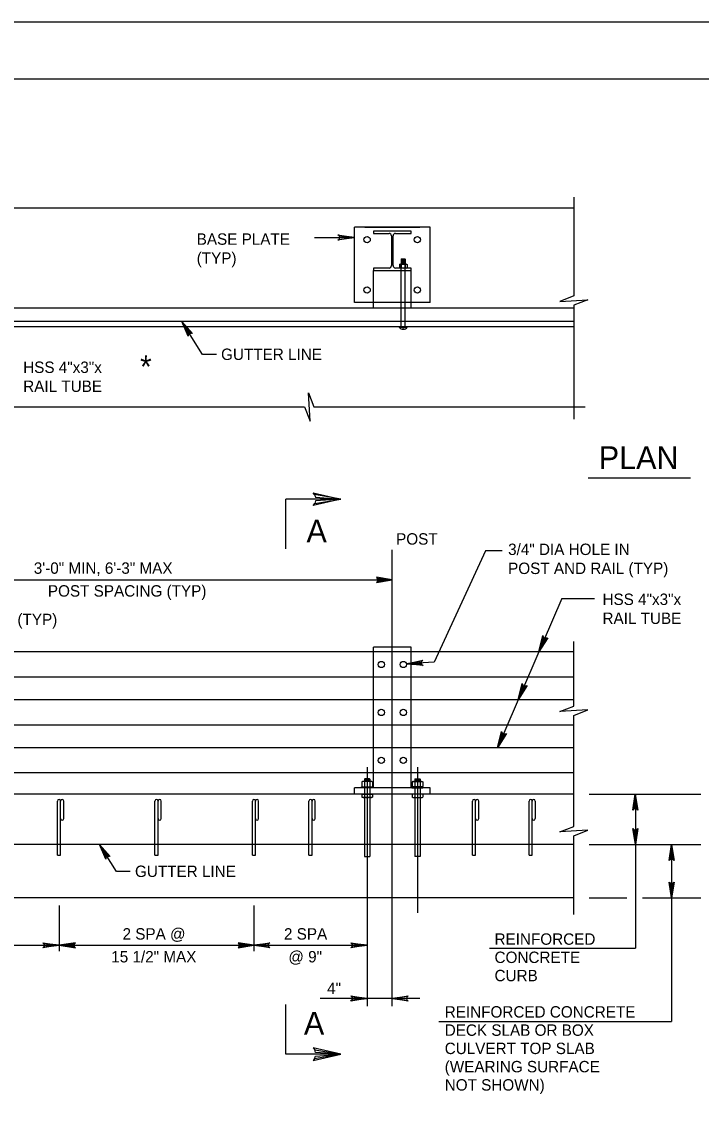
# Model space of a CAD drawing. Extents: x 641054 to 641910, y 298137 to 299325.
# Drawn here: x 641229.9 to 641408.6, y 299039.1 to 299325.4 of the extents above; entities that cross this region are included whole.
import ezdxf

# ---------------------------------------------------------------- set-up
doc = ezdxf.new("R2010")
doc.units = 0
for name, color, linetype in [('1', 7, 'Continuous'), ('2', 7, 'Continuous'), ('Default', 7, 'Continuous'), ('PLT-BNDY', 7, 'Continuous')]:
    doc.layers.add(name, color=color, linetype=linetype)

msp = doc.modelspace()

# ---------------------------------------------------------------- linework, layer by layer
at = {"layer": '1'}
for p, q in [((641329.41, 299261.63), (641329.28, 299261.55)), ((641329.28, 299261.55), (641329.28, 299260.69)), ((641329.41, 299260.61), (641329.28, 299260.69)), ((641329.41, 299261.63), (641331.13, 299261.63)), ((641329.75, 299262.92), (641329.84, 299263.01)), ((641329.75, 299262.92), (641329.75, 299261.63)), ((641329.75, 299262.92), (641330.79, 299262.92)), ((641329.75, 299262.66), (641330.79, 299262.66)), ((641329.75, 299262.4), (641330.79, 299262.4)), ((641329.75, 299262.14), (641330.79, 299262.14)), ((641329.75, 299261.89), (641330.79, 299261.89)), ((641329.75, 299261.55), (641329.75, 299260.69)), ((641329.84, 299263.01), (641330.7, 299263.01)), ((641329.84, 299262.79), (641330.7, 299262.79)), ((641329.84, 299262.53), (641330.7, 299262.53)), ((641329.84, 299262.27), (641330.7, 299262.27)), ((641329.84, 299262.02), (641330.7, 299262.02)), ((641329.84, 299261.76), (641330.7, 299261.76)), ((641330.79, 299262.92), (641330.7, 299263.01)), ((641330.79, 299262.92), (641330.79, 299261.63)), ((641330.79, 299261.55), (641330.79, 299260.69)), ((641331.13, 299261.63), (641331.26, 299261.55)), ((641331.13, 299260.61), (641331.26, 299260.69)), ((641331.26, 299261.55), (641331.26, 299260.69)), ((641331.13, 299260.61), (641329.41, 299260.61)), ((641330.84, 299245.06), (641329.7, 299245.06)), ((641320.04, 299126.17), (641320.16, 299126.29)), ((641320.04, 299126.17), (641320.04, 299125.57)), ((641321.49, 299126.17), (641320.04, 299126.17)), ((641321.37, 299126.29), (641320.16, 299126.29)), ((641321.49, 299126.17), (641321.37, 299126.29)), ((641321.49, 299126.17), (641321.49, 299125.57)), ((641333.27, 299126.17), (641333.39, 299126.29)), ((641333.27, 299126.17), (641333.27, 299125.57)), ((641333.27, 299126.17), (641334.71, 299126.17)), ((641333.39, 299126.29), (641334.59, 299126.29)), ((641334.71, 299126.17), (641334.59, 299126.29)), ((641334.71, 299126.17), (641334.71, 299125.57)), ((641319.56, 299125.57), (641319.37, 299125.46)), ((641319.37, 299125.46), (641319.37, 299124.25)), ((641319.56, 299124.14), (641319.37, 299124.25)), ((641321.97, 299125.57), (641319.56, 299125.57)), ((641321.49, 299125.81), (641320.04, 299125.81)), ((641320.04, 299125.77), (641320.04, 299105.88)), ((641320.04, 299125.46), (641320.04, 299124.25)), ((641321.37, 299125.99), (641320.16, 299125.99)), ((641321.37, 299125.63), (641320.16, 299125.63)), ((641321.49, 299125.77), (641321.49, 299105.88)), ((641321.49, 299125.46), (641321.49, 299124.25)), ((641321.97, 299125.57), (641322.16, 299125.46)), ((641321.97, 299124.14), (641322.16, 299124.25)), ((641322.16, 299125.46), (641322.16, 299124.25)), ((641332.79, 299125.57), (641332.6, 299125.46)), ((641332.6, 299125.46), (641332.6, 299124.25)), ((641332.79, 299124.14), (641332.6, 299124.25)), ((641332.79, 299125.57), (641335.2, 299125.57)), ((641333.27, 299125.81), (641334.71, 299125.81)), ((641333.27, 299125.77), (641333.27, 299105.88)), ((641333.27, 299125.46), (641333.27, 299124.25)), ((641333.38, 299125.99), (641334.6, 299125.99)), ((641333.38, 299125.63), (641334.6, 299125.63)), ((641334.71, 299125.77), (641334.71, 299105.88)), ((641334.71, 299125.46), (641334.71, 299124.25)), ((641335.2, 299125.57), (641335.38, 299125.46)), ((641335.2, 299124.14), (641335.38, 299124.25)), ((641335.38, 299125.46), (641335.38, 299124.25)), ((641319.37, 299122.24), (641319.37, 299121.45)), ((641319.37, 299122.24), (641322.16, 299122.24)), ((641319.56, 299121.34), (641319.37, 299121.45)), ((641321.97, 299121.34), (641319.56, 299121.34)), ((641320.04, 299122.24), (641320.04, 299121.45)), ((641321.49, 299122.24), (641321.49, 299121.45)), ((641321.97, 299121.34), (641322.16, 299121.45)), ((641322.16, 299122.24), (641322.16, 299121.45)), ((641332.6, 299122.24), (641332.6, 299121.45)), ((641335.38, 299122.24), (641332.6, 299122.24)), ((641332.79, 299121.34), (641332.6, 299121.45)), ((641332.79, 299121.34), (641335.2, 299121.34)), ((641333.27, 299122.24), (641333.27, 299121.45)), ((641334.71, 299122.24), (641334.71, 299121.45)), ((641335.2, 299121.34), (641335.38, 299121.45)), ((641335.38, 299122.24), (641335.38, 299121.45)), ((641320.04, 299105.88), (641321.49, 299105.88)), ((641334.71, 299105.88), (641333.27, 299105.88))]:
    msp.add_line(p, q, dxfattribs=at)
for points in [[(641319.32, 299123.9), (641319.32, 299124.14), (641322.21, 299124.14), (641322.21, 299123.9)], [(641335.44, 299123.9), (641335.44, 299124.14), (641332.54, 299124.14), (641332.54, 299123.9)]]:
    msp.add_lwpolyline(points, close=True, dxfattribs=at)
for points in [[(641235.65, 299083.01), (641235.81, 299082.72), (641239.74, 299082.5), (641235.65, 299083.01), (641235.45, 299083.19), (641239.74, 299082.5), (641235.81, 299082.31), (641235.67, 299082.01), (641239.74, 299082.5), (641235.45, 299081.82), (641235.67, 299082.01)], [(641243.83, 299083.01), (641243.68, 299082.72), (641239.74, 299082.5), (641243.83, 299083.01), (641244.04, 299083.19), (641239.74, 299082.5), (641243.67, 299082.31), (641243.82, 299082.01), (641239.74, 299082.5), (641244.04, 299081.82), (641243.82, 299082.01)], [(641316.67, 299083.01), (641316.83, 299082.72), (641320.76, 299082.5), (641316.67, 299083.01), (641316.46, 299083.19), (641320.76, 299082.5), (641316.83, 299082.31), (641316.69, 299082.01), (641320.76, 299082.5), (641316.46, 299081.82), (641316.69, 299082.01)], [(641316.67, 299069.03), (641316.83, 299068.73), (641320.76, 299068.52), (641316.67, 299069.03), (641316.46, 299069.21), (641320.76, 299068.52), (641316.83, 299068.32), (641316.69, 299068.03), (641320.76, 299068.52), (641316.46, 299067.83), (641316.69, 299068.03)]]:
    msp.add_lwpolyline(points, dxfattribs=at)
for centre, radius, start, end in [((641329.52, 299261.22), 0.409, 54.2974, 89.9999), ((641329.52, 299261.02), 0.409, 269.9985, 305.701), ((641330.27, 299259.85), 1.77, 73.0653, 106.9335), ((641330.27, 299262.39), 1.77, 253.0634, 286.9317), ((641331.03, 299261.22), 0.409, 89.9993, 125.7017), ((641331.03, 299261.02), 0.409, 234.2959, 269.9983), ((641319.71, 299124.99), 0.573, 54.2983, 90.0007), ((641319.71, 299124.72), 0.573, 270.0017, 305.7041), ((641320.76, 299123.08), 2.48, 73.0665, 106.9347), ((641320.76, 299126.63), 2.48, 253.0683, 286.9366), ((641321.82, 299124.99), 0.573, 90.0001, 125.7026), ((641321.82, 299124.72), 0.573, 234.299, 270.0015), ((641332.93, 299124.99), 0.573, 54.2974, 89.9999), ((641332.93, 299124.72), 0.573, 269.9985, 305.701), ((641333.99, 299123.08), 2.48, 73.0653, 106.9335), ((641333.99, 299126.63), 2.48, 253.0634, 286.9317), ((641335.05, 299124.99), 0.573, 89.9993, 125.7017), ((641335.05, 299124.72), 0.573, 234.2959, 269.9983), ((641319.71, 299121.91), 0.573, 270.0017, 305.7041), ((641320.76, 299123.82), 2.48, 253.0683, 286.9366), ((641321.82, 299121.91), 0.573, 234.299, 270.0015), ((641332.93, 299121.91), 0.573, 269.9985, 305.701), ((641333.99, 299123.82), 2.48, 253.0634, 286.9317), ((641335.05, 299121.91), 0.573, 234.2959, 269.9983)]:
    msp.add_arc(centre, radius, start, end, dxfattribs=at)
at = {"layer": '2'}
for p, q in [((641094.49, 299310.38), (641880.49, 299310.38)), ((641375.12, 299250.07), (641171.95, 299250.07)), ((641375.12, 299245.11), (641171.08, 299245.11)), ((641378.88, 299205.48), (641405.84, 299205.48)), ((641313.82, 299199.84), (641299.39, 299199.84)), ((641299.39, 299186.74), (641299.39, 299199.84)), ((641371.95, 299173.67), (641355.04, 299134.44)), ((641375.12, 299159.65), (641143.53, 299159.65)), ((641375.12, 299153.04), (641143.53, 299153.04)), ((641375.12, 299147.05), (641143.53, 299147.05)), ((641375.12, 299140.43), (641143.53, 299140.43)), ((641375.12, 299134.44), (641143.53, 299134.44)), ((641375.12, 299127.82), (641143.53, 299127.82)), ((641239.33, 299106.23), (641240.15, 299106.23)), ((641264.96, 299106.23), (641265.78, 299106.23)), ((641290.59, 299106.23), (641291.41, 299106.23)), ((641305.47, 299106.23), (641306.29, 299106.23)), ((641348.46, 299106.23), (641349.29, 299106.23)), ((641363.34, 299106.23), (641364.17, 299106.23)), ((641299.39, 299053.86), (641299.39, 299066.96)), ((641313.82, 299053.86), (641299.39, 299053.86))]:
    msp.add_line(p, q, dxfattribs=at)
for points in [[(641313.31, 299269.18), (641313.46, 299268.87), (641317.46, 299268.65), (641313.31, 299269.18), (641313.09, 299269.36), (641317.46, 299268.65), (641313.46, 299268.46), (641313.32, 299268.16), (641317.46, 299268.65), (641313.09, 299267.96), (641313.32, 299268.16)], [(641281.12, 299237.89), (641277.51, 299237.89), (641272.02, 299246.56)], [(641273.72, 299242.93), (641273.89, 299243.21), (641272.02, 299246.56), (641273.72, 299242.93), (641273.69, 299242.67), (641272.02, 299246.56), (641274.22, 299243.43), (641274.54, 299243.46), (641272.02, 299246.56), (641274.81, 299243.38), (641274.54, 299243.46)], [(641306.96, 299201.08), (641307.21, 299200.37), (641313.82, 299199.84), (641306.96, 299201.08), (641306.61, 299201.52), (641313.82, 299199.84), (641307.22, 299199.37), (641306.98, 299198.66), (641313.82, 299199.84), (641306.61, 299198.19), (641306.98, 299198.66)], [(641356.32, 299186.2), (641351.93, 299186.2), (641338.37, 299156.94), (641331.08, 299156.51)], [(641323.4, 299178.11), (641323.55, 299178.4), (641327.38, 299178.61), (641323.4, 299178.11), (641323.2, 299177.94), (641327.38, 299178.61), (641323.56, 299178.8), (641323.42, 299179.09), (641327.38, 299178.61), (641323.2, 299179.28), (641323.42, 299179.09)], [(641368.03, 299163.26), (641367.69, 299163.24), (641365.91, 299159.65), (641368.03, 299163.26), (641368.28, 299163.38), (641365.91, 299159.65), (641367.31, 299163.4), (641367.09, 299163.65), (641365.91, 299159.65), (641367, 299163.94), (641367.09, 299163.65)], [(641335.26, 299156.24), (641335.08, 299156.53), (641331.08, 299156.51), (641335.26, 299156.24), (641335.48, 299156.07), (641331.08, 299156.51), (641335.06, 299156.95), (641335.18, 299157.25), (641331.08, 299156.51), (641335.4, 299157.47), (641335.18, 299157.25)], [(641362.6, 299150.65), (641362.26, 299150.63), (641360.48, 299147.05), (641362.6, 299150.65), (641362.85, 299150.78), (641360.48, 299147.05), (641361.88, 299150.79), (641361.66, 299151.04), (641360.48, 299147.05), (641361.57, 299151.33), (641361.66, 299151.04)], [(641357.17, 299138.05), (641356.83, 299138.02), (641355.04, 299134.44), (641357.17, 299138.05), (641357.42, 299138.17), (641355.04, 299134.44), (641356.44, 299138.18), (641356.23, 299138.44), (641355.04, 299134.44), (641356.14, 299138.72), (641356.23, 299138.44)], [(641390.79, 299118.27), (641391.07, 299118.42), (641391.28, 299122.24), (641390.79, 299118.27), (641390.61, 299118.07), (641391.28, 299122.24), (641391.47, 299118.42), (641391.76, 299118.28), (641391.28, 299122.24), (641391.95, 299118.07), (641391.76, 299118.28)], [(641391.8, 299112.99), (641391.52, 299112.84), (641391.3, 299109.02), (641391.8, 299112.99), (641391.98, 299113.19), (641391.3, 299109.02), (641391.12, 299112.84), (641390.83, 299112.98), (641391.3, 299109.02), (641390.64, 299113.19), (641390.83, 299112.98)], [(641258.48, 299101.92), (641254.87, 299101.92), (641250.38, 299109.02)], [(641252.08, 299105.39), (641252.25, 299105.67), (641250.38, 299109.02), (641252.08, 299105.39), (641252.04, 299105.13), (641250.38, 299109.02), (641252.58, 299105.89), (641252.9, 299105.92), (641250.38, 299109.02), (641253.17, 299105.84), (641252.9, 299105.92)], [(641400.33, 299105.04), (641400.62, 299105.19), (641400.83, 299109.02), (641400.33, 299105.04), (641400.16, 299104.84), (641400.83, 299109.02), (641401.02, 299105.19), (641401.3, 299105.05), (641400.83, 299109.02), (641401.49, 299104.84), (641401.3, 299105.05)], [(641401.33, 299098.93), (641401.04, 299098.79), (641400.83, 299094.96), (641401.33, 299098.93), (641401.5, 299099.14), (641400.83, 299094.96), (641400.64, 299098.78), (641400.36, 299098.92), (641400.83, 299094.96), (641400.17, 299099.14), (641400.36, 299098.92)], [(641287.03, 299082), (641287.18, 299082.29), (641291, 299082.5), (641287.03, 299082), (641286.82, 299081.83), (641291, 299082.5), (641287.18, 299082.69), (641287.04, 299082.97), (641291, 299082.5), (641286.82, 299083.17), (641287.04, 299082.97)], [(641294.97, 299082), (641294.83, 299082.29), (641291, 299082.5), (641294.97, 299082), (641295.18, 299081.83), (641291, 299082.5), (641294.82, 299082.69), (641294.96, 299082.97), (641291, 299082.5), (641295.18, 299083.17), (641294.96, 299082.97)], [(641331.35, 299068.02), (641331.2, 299068.3), (641327.38, 299068.52), (641331.35, 299068.02), (641331.55, 299067.84), (641327.38, 299068.52), (641331.2, 299068.7), (641331.34, 299068.99), (641327.38, 299068.52), (641331.55, 299069.18), (641331.34, 299068.99)], [(641306.96, 299052.61), (641307.21, 299053.33), (641313.82, 299053.86), (641306.96, 299052.61), (641306.61, 299052.18), (641313.82, 299053.86), (641307.22, 299054.33), (641306.98, 299055.03), (641313.82, 299053.86), (641306.61, 299055.51), (641306.98, 299055.03)]]:
    msp.add_lwpolyline(points, dxfattribs=at)
at = {"layer": 'Default'}
for p, q in [((641375.12, 299279.28), (641375.12, 299253.3)), ((641375.12, 299276.32), (641153.76, 299276.32)), ((641317.46, 299251.52), (641317.46, 299271.36)), ((641337.3, 299271.36), (641317.46, 299271.36)), ((641320.15, 299271.36), (641334.61, 299271.36)), ((641332.34, 299270.32), (641322.42, 299270.32)), ((641322.42, 299270.32), (641322.42, 299269.72)), ((641322.42, 299269.72), (641326.53, 299269.72)), ((641328.23, 299269.72), (641332.34, 299269.72)), ((641332.34, 299269.72), (641332.34, 299270.32)), ((641337.3, 299251.52), (641337.3, 299271.36)), ((641306.89, 299268.65), (641317.46, 299268.65)), ((641327.16, 299269.08), (641327.16, 299261.25)), ((641327.59, 299261.25), (641327.59, 299269.08)), ((641329.75, 299245.11), (641329.75, 299261.63)), ((641330.79, 299245.11), (641330.79, 299261.63)), ((641326.53, 299260.61), (641322.42, 299260.61)), ((641322.42, 299260.61), (641322.42, 299259.99)), ((641322.42, 299259.99), (641332.34, 299259.99)), ((641322.42, 299251.52), (641322.42, 299259.99)), ((641332.34, 299260.61), (641328.23, 299260.61)), ((641332.34, 299259.99), (641332.34, 299260.61)), ((641332.34, 299251.52), (641332.34, 299259.99)), ((641322.42, 299251.52), (641317.46, 299251.52)), ((641322.42, 299250.07), (641322.42, 299251.52)), ((641332.34, 299251.52), (641322.42, 299251.52)), ((641337.3, 299251.52), (641332.34, 299251.52)), ((641332.34, 299250.07), (641332.34, 299251.52)), ((641375.12, 299250.82), (641375.12, 299220.84)), ((641375.12, 299246.56), (641167.1, 299246.56)), ((641329.21, 299245.06), (641329.76, 299245.06)), ((641329.21, 299245.05), (641329.21, 299245.06)), ((641329.21, 299245.05), (641329.76, 299245.05)), ((641329.76, 299245.05), (641329.76, 299245.06)), ((641330.78, 299245.06), (641329.76, 299245.06)), ((641330.78, 299245.06), (641330.78, 299245.05)), ((641330.78, 299245.06), (641331.33, 299245.06)), ((641330.78, 299245.05), (641331.33, 299245.05)), ((641201.41, 299224.08), (641304.27, 299224.08)), ((641306.75, 299224.08), (641378.13, 299224.08)), ((641327.38, 299066.46), (641327.38, 299186.47)), ((641153.76, 299178.61), (641327.38, 299178.61)), ((641371.95, 299173.67), (641380.56, 299173.67)), ((641322.42, 299159.65), (641322.42, 299160.89)), ((641332.34, 299160.89), (641322.42, 299160.89)), ((641332.34, 299159.65), (641332.34, 299160.89)), ((641375.12, 299145.41), (641375.12, 299162.4)), ((641322.42, 299153.04), (641322.42, 299159.65)), ((641332.34, 299153.04), (641332.34, 299159.65)), ((641322.42, 299147.05), (641322.42, 299153.04)), ((641332.34, 299147.05), (641332.34, 299153.04)), ((641322.42, 299140.43), (641322.42, 299147.05)), ((641332.34, 299140.43), (641332.34, 299147.05)), ((641322.42, 299134.44), (641322.42, 299140.43)), ((641332.34, 299134.44), (641332.34, 299140.43)), ((641375.12, 299113.78), (641375.12, 299142.93)), ((641322.42, 299127.83), (641322.42, 299134.44)), ((641332.34, 299127.83), (641332.34, 299134.44)), ((641320.76, 299129.37), (641320.76, 299066.46)), ((641333.99, 299129.37), (641333.99, 299091.05)), ((641322.42, 299123.9), (641322.42, 299127.82)), ((641332.34, 299123.9), (641332.34, 299127.82)), ((641337.3, 299123.9), (641317.46, 299123.9)), ((641317.46, 299122.24), (641317.46, 299123.9)), ((641337.3, 299122.24), (641337.3, 299123.9)), ((641375.12, 299122.24), (641153.76, 299122.24)), ((641239.33, 299106.23), (641239.33, 299120.43)), ((641240.15, 299106.23), (641240.15, 299120.43)), ((641240.98, 299115.82), (641240.98, 299120.43)), ((641264.96, 299106.23), (641264.96, 299120.43)), ((641265.78, 299106.23), (641265.78, 299120.43)), ((641266.61, 299115.82), (641266.61, 299120.43)), ((641290.59, 299106.23), (641290.59, 299120.43)), ((641291.41, 299106.23), (641291.41, 299120.43)), ((641292.24, 299115.82), (641292.24, 299120.43)), ((641305.47, 299106.23), (641305.47, 299120.43)), ((641306.29, 299106.23), (641306.29, 299120.43)), ((641307.12, 299115.82), (641307.12, 299120.43)), ((641348.46, 299106.23), (641348.46, 299120.43)), ((641349.29, 299106.23), (641349.29, 299120.43)), ((641350.11, 299115.82), (641350.11, 299120.43)), ((641363.34, 299106.23), (641363.34, 299120.43)), ((641364.17, 299106.23), (641364.17, 299120.43)), ((641365, 299115.82), (641365, 299120.43)), ((641379.19, 299122.24), (641408.52, 299122.24)), ((641391.3, 299122.24), (641391.3, 299081.75)), ((641239.33, 299118.12), (641239.33, 299118.95)), ((641264.96, 299118.12), (641264.96, 299118.95)), ((641290.59, 299118.12), (641290.59, 299118.95)), ((641305.47, 299118.12), (641305.47, 299118.95)), ((641348.46, 299118.12), (641348.46, 299118.95)), ((641363.34, 299118.12), (641363.34, 299118.95)), ((641239.33, 299114.61), (641239.33, 299115.43)), ((641264.96, 299114.61), (641264.96, 299115.43)), ((641290.59, 299114.61), (641290.59, 299115.43)), ((641305.47, 299114.61), (641305.47, 299115.43)), ((641348.46, 299114.61), (641348.46, 299115.43)), ((641363.34, 299114.61), (641363.34, 299115.43)), ((641375.12, 299109.02), (641153.76, 299109.02)), ((641375.12, 299090.56), (641375.12, 299111.3)), ((641379.19, 299109.02), (641408.52, 299109.02)), ((641400.83, 299109.02), (641400.83, 299062.45)), ((641375.12, 299094.96), (641153.76, 299094.96)), ((641379.19, 299094.96), (641389.04, 299094.96)), ((641393.22, 299094.96), (641408.52, 299094.96)), ((641239.74, 299092.98), (641239.74, 299080.98)), ((641291, 299092.98), (641291, 299080.98)), ((641209.98, 299082.5), (641320.76, 299082.5)), ((641352.95, 299081.75), (641391.3, 299081.75)), ((641334.65, 299068.52), (641308.39, 299068.52)), ((641339.63, 299062.45), (641400.83, 299062.45))]:
    msp.add_line(p, q, dxfattribs=at)
for points in [[(641375.12, 299253.3), (641371.4, 299251.79), (641378.84, 299252.24), (641375.12, 299250.82)], [(641304.27, 299224.08), (641305.78, 299220.36), (641305.33, 299227.8), (641306.75, 299224.08)], [(641375.12, 299142.93), (641378.84, 299144.44), (641371.4, 299143.99), (641375.12, 299145.41)], [(641375.12, 299111.3), (641378.84, 299112.81), (641371.4, 299112.36), (641375.12, 299113.78)]]:
    msp.add_lwpolyline(points, dxfattribs=at)
for centre, radius in [((641320.76, 299268.05), 0.827), ((641333.99, 299268.05), 0.827), ((641320.76, 299254.82), 0.827), ((641333.99, 299254.82), 0.827), ((641324.48, 299156.34), 0.826), ((641330.27, 299156.34), 0.826), ((641324.48, 299143.73), 0.826), ((641330.27, 299143.73), 0.826), ((641324.48, 299131.13), 0.826), ((641330.27, 299131.13), 0.826)]:
    msp.add_circle(centre, radius, dxfattribs=at)
for centre, radius, start, end in [((641326.53, 299269.08), 0.636, 0, 90), ((641328.23, 299269.08), 0.636, 90, 180), ((641326.53, 299261.25), 0.636, 270, 0), ((641328.23, 299261.25), 0.636, 180, 270), ((641330.27, 299245.83), 1.32, 216.3703, 323.6297), ((641329.7, 299245.11), 0.0512, 269.9973, 357.2783), ((641330.27, 299245.83), 0.931, 236.9318, 303.0682), ((641330.84, 299245.11), 0.0512, 182.7217, 270.0027), ((641239.74, 299120.43), 0.413, 0, 180), ((641240.57, 299120.43), 0.413, 0, 180), ((641265.37, 299120.43), 0.413, 0, 180), ((641266.2, 299120.43), 0.413, 0, 180), ((641291, 299120.43), 0.413, 0, 180), ((641291.83, 299120.43), 0.413, 0, 180), ((641305.88, 299120.43), 0.413, 0, 180), ((641306.71, 299120.43), 0.413, 0, 180), ((641348.87, 299120.43), 0.413, 0, 180), ((641349.7, 299120.43), 0.413, 0, 180), ((641363.75, 299120.43), 0.413, 0, 180), ((641364.58, 299120.43), 0.413, 0, 180), ((641240.57, 299115.82), 0.413, 180, 0), ((641266.2, 299115.82), 0.413, 180, 0), ((641291.83, 299115.82), 0.413, 180, 0), ((641306.71, 299115.82), 0.413, 180, 0), ((641349.7, 299115.82), 0.413, 180, 0), ((641364.58, 299115.82), 0.413, 180, 0)]:
    msp.add_arc(centre, radius, start, end, dxfattribs=at)
for points, degree in [([(641329.79, 299245.06), (641329.78, 299245.06), (641329.76, 299245.07), (641329.75, 299245.1), (641329.75, 299245.11), (641329.75, 299245.11)], 3), ([(641329.75, 299245.11), (641329.75, 299245.11)], 1), ([(641330.79, 299245.11), (641330.79, 299245.11), (641330.79, 299245.1), (641330.78, 299245.07), (641330.76, 299245.06), (641330.75, 299245.06)], 3), ([(641330.79, 299245.11), (641330.79, 299245.11)], 1), ([(641331.33, 299245.06), (641331.33, 299245.05)], 1)]:
    msp.add_open_spline(points, degree=degree, dxfattribs=at)
at = {"layer": 'PLT-BNDY'}
msp.add_lwpolyline([(641054.49, 299325.38), (641895.49, 299325.38), (641895.49, 298731.38), (641054.49, 298731.38)], close=True, dxfattribs=at)

# ---------------------------------------------------------------- texts
at = {"layer": '2'}
for s, height, p in [('BASE PLATE', 3, (641275.95, 299266.73)), ('(TYP)', 3, (641275.95, 299261.73)), ('GUTTER LINE', 3, (641282.36, 299236.43)), ('HSS 4"x3"x', 3, (641230.32, 299233.02)), ('*', 5.88, (641261.05, 299231.74)), ('RAIL TUBE', 3, (641230.32, 299228.02)), ('PLAN', 6, (641381.69, 299207.74)), ('  POST', 3, (641326.16, 299187.87)), ('3/4" DIA HOLE IN', 3, (641357.84, 299185.14)), ('3\'-0" MIN, 6\'-3" MAX', 3.0001, (641233.11, 299180.2)), ('POST AND RAIL (TYP)', 3, (641357.84, 299180.14)), ('POST SPACING (TYP)', 3.0001, (641236.82, 299174.2)), ('HSS 4"x3"x', 3, (641382.66, 299172)), ('RAIL TUBE', 3, (641382.66, 299167)), ('GUTTER LINE', 3, (641259.72, 299100.46)), ('2 SPA @', 3, (641256.45, 299084)), ('2 SPA', 3, (641298.9, 299084)), ('REINFORCED', 3, (641354.27, 299082.64)), ('15 1/2" MAX', 3.0001, (641253.48, 299078)), ('@ 9"', 3, (641300.06, 299078)), ('CONCRETE', 3, (641354.27, 299077.84)), ('CURB', 3, (641354.27, 299073.04)), ('4"', 3, (641310.25, 299069.71)), ('REINFORCED CONCRETE', 3.0001, (641341.17, 299063.49)), ('DECK SLAB OR BOX', 3.0001, (641341.17, 299058.69)), ('CULVERT TOP SLAB', 3.0001, (641341.17, 299053.89)), ('(WEARING SURFACE', 3.0001, (641341.17, 299049.09)), ('NOT SHOWN)', 3, (641341.17, 299044.29))]:
    msp.add_text(s, height=height, dxfattribs=at).set_placement(p)
for s, height, p in [('A', 6, (641304.82, 299188.44)), ('1 3/4" (TYP)', 3, (641217.35, 299166.7)), ('A', 6, (641304.14, 299059))]:
    msp.add_text(s, height=height, rotation=360, dxfattribs=at).set_placement(p)

doc.saveas('drawing.dxf')
